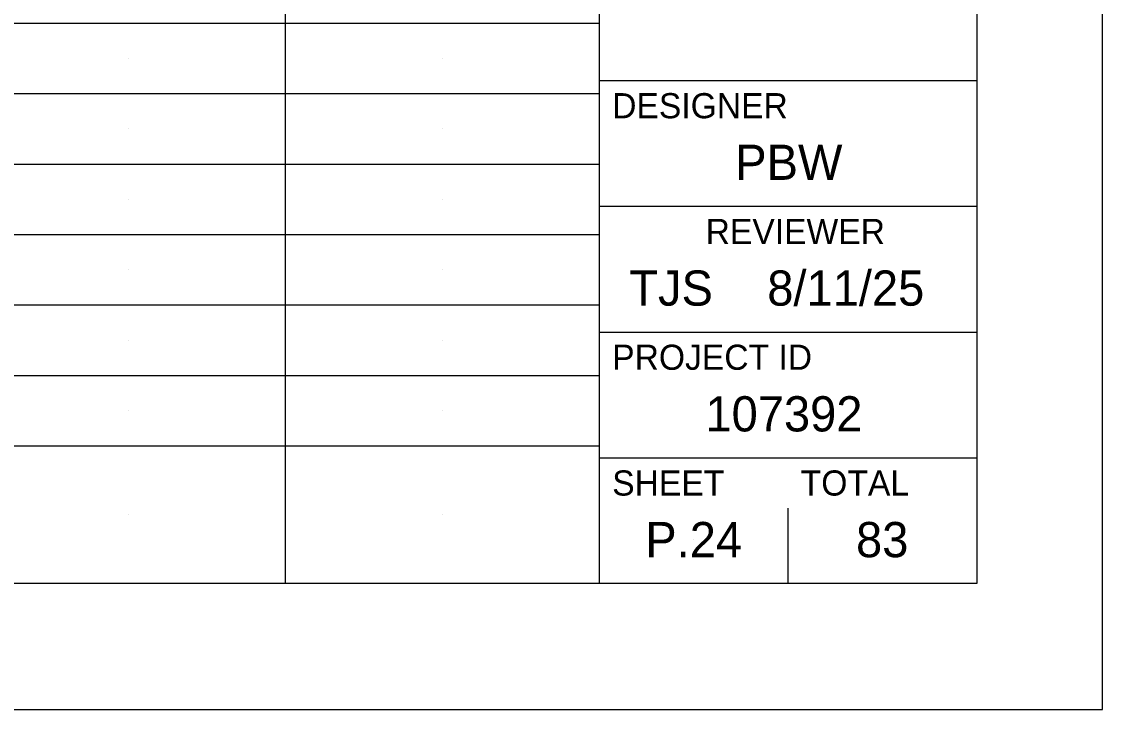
# Model space of a CAD drawing. Extents: x 0 to 66.4, y -22.2 to 22.
# Drawn here: x 29.701 to 34, y 0 to 2.734 of the extents above; entities that cross this region are included whole.
import ezdxf

# ---------------------------------------------------------------- set-up
doc = ezdxf.new("R2010")
doc.units = 0
for name, color, linetype in [('SC_Scratch1', 7, 'Continuous'), ('SC_Scratch3', 7, 'Continuous'), ('SH_Border', 7, 'Continuous'), ('SH_Cut_Line', 7, 'Continuous'), ('SH_Data', 7, 'Continuous')]:
    doc.layers.add(name, color=color, linetype=linetype)

msp = doc.modelspace()

# ---------------------------------------------------------------- linework, layer by layer
at = {"layer": 'SC_Scratch1'}
for p, q in [((30.125, 2.588), (30.125, 2.588)), ((31.375, 2.588), (31.375, 2.588)), ((30.125, 2.308), (30.125, 2.308)), ((31.375, 2.308), (31.375, 2.308)), ((30.125, 2.028), (30.125, 2.028)), ((31.375, 2.028), (31.375, 2.028)), ((30.125, 1.748), (30.125, 1.748)), ((31.375, 1.748), (31.375, 1.748)), ((30.125, 1.468), (30.125, 1.468)), ((31.375, 1.468), (31.375, 1.468)), ((30.125, 1.188), (30.125, 1.188)), ((31.375, 1.188), (31.375, 1.188))]:
    msp.add_line(p, q, dxfattribs=at)
at = {"layer": 'SC_Scratch3'}
for p, q in [((30.125, 0.774), (30.125, 0.774)), ((31.375, 0.774), (31.375, 0.774))]:
    msp.add_line(p, q, dxfattribs=at)
at = {"layer": 'SH_Border'}
for p, q in [((32, 0.5), (32, 21.5)), ((32, 2.5), (33.5, 2.5)), ((32, 2), (33.5, 2)), ((32, 1.5), (33.5, 1.5)), ((32, 1), (33.5, 1))]:
    msp.add_line(p, q, dxfattribs=at)
msp.add_lwpolyline([(1.5, 21.5), (33.5, 21.5), (33.5, 0.5), (1.5, 0.5)], close=True, dxfattribs=at)
at = {"layer": 'SH_Cut_Line'}
msp.add_lwpolyline([(0, 0), (34, 0), (34, 22), (0, 22)], close=True, dxfattribs=at)
at = {"layer": 'SH_Data'}
for p, q in [((30.75, 0.5), (30.75, 21.5)), ((1.5, 2.728), (32, 2.728)), ((1.5, 2.448), (32, 2.448)), ((1.5, 2.168), (32, 2.168)), ((1.5, 1.888), (32, 1.888)), ((1.5, 1.608), (32, 1.608)), ((1.5, 1.328), (32, 1.328)), ((1.5, 1.048), (32, 1.048)), ((32.75, 0.5), (32.75, 0.8)), ((32.375, 0.675), (32.375, 0.675))]:
    msp.add_line(p, q, dxfattribs=at)

# ---------------------------------------------------------------- texts
for s, height, p in [('DESIGNER', 0.1, (32.05, 2.35)), ('PBW', 0.14, (32.5395, 2.105)), ('REVIEWER', 0.1, (32.4218, 1.85)), ('TJS', 0.14, (32.1179, 1.605)), ('8/11/25', 0.14, (32.6669, 1.605)), ('PROJECT ID', 0.1, (32.05, 1.35)), ('107392', 0.14, (32.4209, 1.105)), ('SHEET', 0.1, (32.05, 0.85)), ('TOTAL', 0.1, (32.8, 0.85)), ('P.24', 0.14, (32.1816, 0.605)), ('83', 0.14, (33.02, 0.605))]:
    msp.add_text(s, height=height, dxfattribs=at).set_placement(p)

doc.saveas('drawing.dxf')
